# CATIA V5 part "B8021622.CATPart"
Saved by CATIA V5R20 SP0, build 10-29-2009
Part number: B8021622
Revision: 14
Definition: design
Nomenclature: B8021622
Source: made
Description: NOT SPECIFIED
Bounding box of the stored display mesh (mm): x -16 to 16, y -16 to 16, z -8 to 22
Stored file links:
  C:\Users\Utente\Desktop\3D files B802\B8021622.CATPart
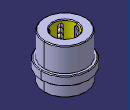
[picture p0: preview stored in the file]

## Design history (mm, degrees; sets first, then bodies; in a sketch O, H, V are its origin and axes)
Body1 "MANIFOLD_SOLID_BREP #38" (main body)
  Solid1: solid without history
Body2 "MANIFOLD_SOLID_BREP #76"
  Solid2: solid without history
Body3 "MANIFOLD_SOLID_BREP #114"
  Solid3: solid without history
Body4 "MANIFOLD_SOLID_BREP #152"
  Solid4: solid without history
Body5 "MANIFOLD_SOLID_BREP #190"
  Solid5: solid without history
Body6 "MANIFOLD_SOLID_BREP #228"
  Solid6: solid without history
Body7 "MANIFOLD_SOLID_BREP #266"
  Solid7: solid without history
Body8 "MANIFOLD_SOLID_BREP #304"
  Solid8: solid without history
Body9 "MANIFOLD_SOLID_BREP #2006"
  Solid9: solid without history
Body10 "MANIFOLD_SOLID_BREP #2044"
  Solid10: solid without history
Body11 "MANIFOLD_SOLID_BREP #2082"
  Solid11: solid without history
Body12 "MANIFOLD_SOLID_BREP #2120"
  Solid12: solid without history
Body13 "MANIFOLD_SOLID_BREP #2158"
  Solid13: solid without history
Body14 "MANIFOLD_SOLID_BREP #2196"
  Solid14: solid without history
Body15 "MANIFOLD_SOLID_BREP #2234"
  Solid15: solid without history
Body16 "MANIFOLD_SOLID_BREP #2272"
  Solid16: solid without history
Body17 "MANIFOLD_SOLID_BREP #2310"
  Solid17: solid without history
Body18 "MANIFOLD_SOLID_BREP #2348"
  Solid18: solid without history
Body19 "MANIFOLD_SOLID_BREP #2386"
  Solid19: solid without history
Body20 "MANIFOLD_SOLID_BREP #2424"
  Solid20: solid without history
Body21 "MANIFOLD_SOLID_BREP #2462"
  Solid21: solid without history
Body22 "MANIFOLD_SOLID_BREP #2500"
  Solid22: solid without history
Body23 "MANIFOLD_SOLID_BREP #2538"
  Solid23: solid without history
Body24 "MANIFOLD_SOLID_BREP #2576"
  Solid24: solid without history
Body25 "MANIFOLD_SOLID_BREP #2614"
  Solid25: solid without history
Body26 "MANIFOLD_SOLID_BREP #2652"
  Solid26: solid without history
Body27 "MANIFOLD_SOLID_BREP #2690"
  Solid27: solid without history
Body28 "MANIFOLD_SOLID_BREP #2728"
  Solid28: solid without history
Body29 "MANIFOLD_SOLID_BREP #2766"
  Solid29: solid without history
Body30 "MANIFOLD_SOLID_BREP #2804"
  Solid30: solid without history
Body31 "MANIFOLD_SOLID_BREP #2842"
  Solid31: solid without history
Body32 "MANIFOLD_SOLID_BREP #2880"
  Solid32: solid without history
Body33 "MANIFOLD_SOLID_BREP #2918"
  Solid33: solid without history
Body34 "MANIFOLD_SOLID_BREP #2956"
  Solid34: solid without history
Body35 "MANIFOLD_SOLID_BREP #2994"
  Solid35: solid without history
Body36 "MANIFOLD_SOLID_BREP #3032"
  Solid36: solid without history
Body37 "MANIFOLD_SOLID_BREP #3070"
  Solid37: solid without history
Body38 "MANIFOLD_SOLID_BREP #3108"
  Solid38: solid without history
Body39 "MANIFOLD_SOLID_BREP #3146"
  Solid39: solid without history
Body40 "MANIFOLD_SOLID_BREP #3184"
  Solid40: solid without history
Body41 "MANIFOLD_SOLID_BREP #3222"
  Solid41: solid without history
Body42 "MANIFOLD_SOLID_BREP #3260"
  Solid42: solid without history
Body43 "MANIFOLD_SOLID_BREP #3298"
  Solid43: solid without history
Body44 "MANIFOLD_SOLID_BREP #3336"
  Solid44: solid without history
Body45 "MANIFOLD_SOLID_BREP #3374"
  Solid45: solid without history
Body46 "MANIFOLD_SOLID_BREP #3412"
  Solid46: solid without history
Body47 "MANIFOLD_SOLID_BREP #3450"
  Solid47: solid without history
Body48 "MANIFOLD_SOLID_BREP #3488"
  Solid48: solid without history
Body49 "MANIFOLD_SOLID_BREP #3526"
  Solid49: solid without history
